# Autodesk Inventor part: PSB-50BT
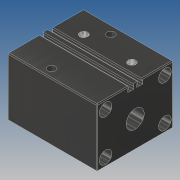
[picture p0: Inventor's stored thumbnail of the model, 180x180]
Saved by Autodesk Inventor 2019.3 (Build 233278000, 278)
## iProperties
Created: 2010-02
Part Number: PSB-50BT
Material: Ogólny
Document SubType Name: Modeling
Designer: CADENGINEERING4
Density: 1 g/cm^3
Appearance: Ciemnoszara
Author: CADENGINEERING4
Revision Number: 1LAST_VERSION
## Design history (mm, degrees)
feature "Baza1"
sketch "Szkic1"
  geometry: C1 r 4.25 at (74.5, 54.5) reference; C2 r 4.25 at (74.5, 8.5) reference; C3 r 4.25 at (8.5, 54.5) reference; C4 r 4.25 at (8.5, 8.5) reference; 1 further point
sketch "Szkic2"
  geometry: L1 (3.065, 59.927)-(13.614, 59.927); L2 (13.614, 59.927)-(13.614, 3.095); L3 (13.614, 3.095)-(3.065, 3.095); L4 (3.065, 3.095)-(3.065, 59.927); L5 (70.25, 59.83)-(79.932, 59.83); L6 (79.932, 59.83)-(79.932, 3.095); L7 (79.932, 3.095)-(69.452, 3.095); L8 (69.452, 3.095)-(69.452, 59.516); L9 (69.452, 59.516)-(69.452, 59.83); L10 (69.452, 59.83)-(70.25, 59.83); 1 further point
  constraints: 20 end point, 3 perpendicular, 2 horizontal, 2 parallel, 1 point on line
extrude "Wyciągnięcie proste1" join sketch "Szkic2" distance "d0" = 30; taper "d1" = 0 deg
hole "Otwór1" sketch "Szkic1" diameter "d2" = 8.376; stored, may be unused: countersink angle "d6" = 90 deg, drill point angle "d8" = 0 deg; dims "d3" = 20, "d4" = 4, "d5" = 2, "d7" = 27.3
node "Bryła1"
